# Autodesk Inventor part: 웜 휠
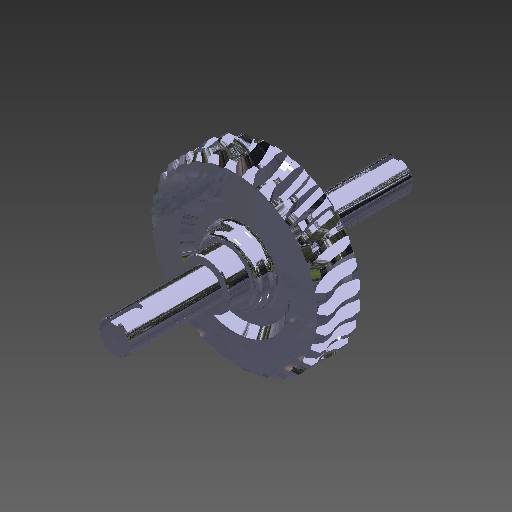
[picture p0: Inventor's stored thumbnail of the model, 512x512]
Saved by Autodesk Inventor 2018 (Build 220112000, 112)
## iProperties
Created: 2013-01
Part Number: 웜 휠
Material: 탄소강
Document SubType Name: Modeling
Designer: 한국산업디자인학원[gmhk.co.kr]
Categories: <?xml version="1.0" encoding="UTF-16"?> <MemberInstance><Categories><FamilyTemplate><FamilyTemplateParameter ValueType="xs:double" Id="1" ObjectReferenceKey="da
Density: 7.87 g/cm^3
Mass: 6989.44 g
Surface Area: 1041.74 cm^2
Volume: 888.112 cm^3
Appearance: _시험-파란색 크롬
CustomPartVersion: 1
Author: 한국산업디자인학원[gmhk.co.kr]
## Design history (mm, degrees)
body "Solid1"
node "톱니 평면"
sketch "기본 본체 스케치"
  geometry: L1 (0, -14)-(0, 14) reference; L2 (0, 20)-(77.639, 20); L3 (77.639, 20)-(82.5, 15.652); L4 (-10, 0)-(60, 0) reference; L5 (82.5, 15.652)-(82.5, -15.652); L6 (0, -20)-(77.639, -20); L7 (0, 20)-(0, -20); L8 (77.639, -20)-(82.5, -15.652); C1 r 20 at (100, 0)
  constraints: 14 end point, 3 symmetric about line, 2 perpendicular, 2 point on line, 1 centre point, 1 collinear
  dimensions: "d50" = 41.8103 deg angle of L3 L2 (= da_fi); "d87" = 165 diameter of L5 L1 (= da_dae); "d89" = 40 diameter of C1 (= 2 x da_aw - da_da); "d92" = 40 distance of L2.start L6.start (= da_b); "d93" = 100 distance from line of C1.centre L7 (= da_aw)
revolve "기본 본체" stored, may be unused: angle "d35" = 90 deg
revolve "기본 본체2" stored, may be unused: angle "d90" = 90 deg
workplane "Work Plane13"
revolve "톱니" stored, may be unused: angle "d43" = 90 deg
pattern_circular "톱니 패턴" dims angle "d46" = 360 deg
workplane "Work Plane14"
workplane "Work Plane15"
revolve "회전6" stored, may be unused: angle "d97" = 90 deg
revolve "회전7" stored, may be unused: angle "d104" = 90 deg
fillet "모깎기1" dims "d105" = 5
chamfer "모따기1" distance "d106" = 1; stored, may be unused: second distance "d107" = 2, angle "d108" = 45 deg
node "작업 평면16"
sketch "스케치11"
  geometry: L1 (-14, 43)-(14, 43) reference; L2 (4, 43)-(4, 22); L3 (-4, 22)-(-4, 43); A1 r 4 centre (0, 22) between (-4, 22) and (4, 22); 2 further points
  constraints: 4 end point, 2 perpendicular, 2 point on circle, 2 point on line, 2 tangent, 1 centre point, 1 midpoint, 1 vertical alignment
  dimensions: "d109" = 8 distance between parallel lines of L2 L3; "d110" = 25 dimension on A1 L1
extrude "돌출1" cut sketch "스케치11" distance "d111" = 4; taper "d112" = 0 deg
mirror "대칭1"
sketch "톱니 스케치"
  geometry: L1 (10, 5.301)-(10, -5.301) reference; L2 (-32.842, 0)-(-12.948, 0) reference; L3 (-90, 6.896)-(-90, -6.896); L4 (-90, -6.896)-(-71, -6.896); L5 (-71, -6.896)-(-59, -2.529); L6 (-59, -2.529)-(-59, 0); L7 (-59, 2.529)-(-71, 6.896); L8 (-71, 6.896)-(-90, 6.896); L9 (-59, 2.529)-(-59, 0); L10 (-65, 0)-(-65, -4.712)
  constraints: 16 end point, 4 perpendicular, 3 equal length, 2 point on line, 1 midpoint, 1 parallel, 1 vertical
  dimensions: "d38" = 100 distance between parallel lines of L1 L3 (= da_aw); "d39" = 20 deg angle of L7 L8 (= da_alfat); "d40" = 19 distance of L7.end L3.start (= 0.5 x da_df1); "d41" = 25 distance between parallel lines of L3 L10 (= 0.5 x da_d1); "d42" = 4.71239 distance of L10.start L10.end (= 0.3 x da_px)
sketch "Sketch8"
  geometry: C1 r 77.639 at (0, 0) reference; C2 r 75 at (0, 0)
  constraints: 1 centre point, 1 coincident
  dimensions: "d77" = 150 diameter of C2 (= da_dw)
body "Srf1"
sketch "스케치9"
  geometry: L1 (-74.283, 20)-(-74.054, 20) reference; L2 (-74.054, 20)-(-74.261, 20) reference; L3 (-74.261, 20)-(-75.727, 20) reference; L4 (-77.355, 20)-(-75.727, 20) reference; L5 (-77.355, 20)-(-77.106, 20) reference; L6 (-77.106, 20)-(-76.222, 20) reference; L7 (-76.222, 20)-(-77.633, 20) reference; L8 (-77.045, 20)-(-77.633, 20) reference; L9 (-77.045, 20)-(-76.789, 20) reference; L10 (-76.789, 20)-(-74.852, 20) reference; L11 (-74.852, 20)-(-76.145, 20) reference; L12 (-73.369, 20)-(-76.145, 20) reference; L13 (-73.369, 20)-(-73.116, 20) reference; L14 (-73.116, 20)-(-70.211, 20) reference; L15 (-70.211, 20)-(-71.33, 20) reference; L16 (-66.486, 20)-(-71.33, 20) reference; L17 (-66.486, 20)-(-66.247, 20) reference; L18 (-66.247, 20)-(-62.501, 20) reference; L19 (-62.501, 20)-(-63.397, 20) reference; L20 (-56.697, 20)-(-63.397, 20) reference; L21 (-56.697, 20)-(-56.483, 20) reference; L22 (-56.483, 20)-(-52.059, 20) reference; L23 (-52.059, 20)-(-52.693, 20) reference; L24 (-44.431, 20)-(-52.693, 20) reference; L25 (-44.431, 20)-(-44.25, 20) reference; L26 (-44.25, 20)-(-39.342, 20) reference; L27 (-39.342, 20)-(-39.687, 20) reference; L28 (-30.222, 20)-(-39.687, 20) reference; L29 (-30.222, 20)-(-30.084, 20) reference; L30 (-30.084, 20)-(-24.906, 20) reference; L31 (-24.906, 20)-(-24.945, 20) reference; L32 (-14.693, 20)-(-24.945, 20) reference; L33 (-14.693, 20)-(-14.602, 20) reference; L34 (-14.602, 20)-(-9.381, 20) reference; L35 (-9.381, 20)-(-9.114, 20) reference; L36 (1.479, 20)-(-9.114, 20) reference; L37 (1.479, 20)-(1.517, 20) reference; L38 (1.517, 20)-(6.554, 20) reference; L39 (6.554, 20)-(7.116, 20) reference; L40 (17.586, 20)-(7.116, 20) reference; L41 (17.586, 20)-(17.571, 20) reference; L42 (17.571, 20)-(22.202, 20) reference; L43 (22.202, 20)-(23.034, 20) reference; L44 (32.924, 20)-(23.034, 20) reference; L45 (32.924, 20)-(32.856, 20) reference; L46 (32.856, 20)-(36.88, 20) reference; L47 (36.88, 20)-(37.946, 20) reference; L48 (46.823, 20)-(37.946, 20) reference; L49 (46.823, 20)-(46.705, 20) reference; L50 (46.705, 20)-(49.946, 20) reference; L51 (49.946, 20)-(51.2, 20) reference; L52 (58.676, 20)-(51.2, 20) reference; L53 (58.676, 20)-(58.514, 20) reference; L54 (58.514, 20)-(60.83, 20) reference; L55 (60.83, 20)-(62.216, 20) reference; L56 (67.965, 20)-(62.216, 20) reference; L57 (67.965, 20)-(67.764, 20) reference; L58 (67.764, 20)-(69.055, 20) reference; L59 (69.055, 20)-(70.512, 20) reference; L60 (74.283, 20)-(70.512, 20) reference; L61 (74.283, 20)-(74.054, 20) reference; L62 (74.054, 20)-(74.261, 20) reference; L63 (74.261, 20)-(75.727, 20) reference; L64 (77.355, 20)-(75.727, 20) reference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
  constraints: 8 end point, 3 point on line, 2 perpendicular, 1 parallel
  dimensions: "d94" = 90 diameter of L122.end L121; "d95" = 135 deg angle of L123 L122; "d96" = 13 distance from line of L121.start L122
node "투영된 루프1"
sketch "스케치10"
  geometry: L1 (45, 13)-(-45, 13) reference; L2 (0, 13)-(0, 133); L3 (0, 133)-(-15, 133); L4 (-15, 133)-(-15, 47); L5 (-15, 47)-(-22.5, 47); L6 (-22.5, 47)-(-22.5, 28); L7 (-22.5, 28)-(-30, 28); L8 (-30, 28)-(-30, 13); L9 (30, 47)-(-30, 47) reference; 1 further point
  constraints: 14 end point, 4 parallel, 3 perpendicular, 1 collinear, 1 midpoint, 1 point on line
  dimensions: "d99" = 30 diameter of L4 L2; "d100" = 45 diameter of L6 L2; "d101" = 60 diameter of L8 L2; "d102" = 15 distance between parallel lines of L7 L1; "d103" = 120 distance of L2.start L2.end
node "참조1"
feature "피치 지름" dims "d78" = 40 (= da_b), "d79" = 0
other parameters: "da_aw" = 100 [user parameter; used in 5 equation terms], "da_fi" = 41.8103 deg [user parameter; used in 1 equation term], "da_b" = 40 [user parameter; used in 2 equation terms], "da_df" = 138 [user parameter], "da_beta" = 1.97396 [user parameter; used in 1 equation term], "da_alfat" = 20 deg [user parameter; used in 1 equation term], "da_df1" = 38 [user parameter; used in 1 equation term], "da_px" = 90 deg [user parameter; used in 1 equation term], "d37" = -1.97396 (computed from da_rightdir, da_beta), "d69" = 0, "d73" = 0, "d75" = 6 deg (computed from da_z), "da_dw" = 150 [user parameter; used in 1 equation term], "da_rightdir" = 0 [user parameter; used in 1 equation term], "d80" = 0, "d81" = 0, "d82" = 0, "d83" = 6 deg (computed from da_z), "d84" = 0, "d85" = 180 deg, "da_dae" = 165 [user parameter; used in 1 equation term]
